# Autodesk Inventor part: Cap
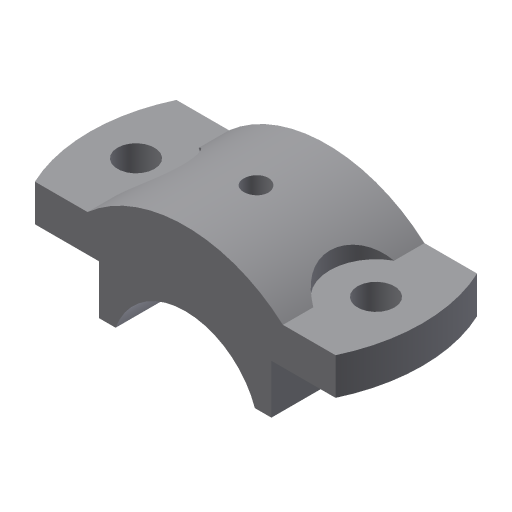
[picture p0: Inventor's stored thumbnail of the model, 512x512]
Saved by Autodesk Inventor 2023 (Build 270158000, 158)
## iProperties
Created: 2002-02
Part Number: Cap
Document SubType Name: Modeling
Designer: ***
Density: 1 g/cm^3
Material: Generic
Appearance: Default
Control State: 0
Master: False
Checked Out: False
Shininess: 77.0
Angle Display Precision: 2
Document Length Units: 11269
Document Angle Units: 11279
Document Time Units: 11290
Document Mass Units: 11283
Document Length Units Precision: 3
Document Angle Units Precision: 2
Density: 0.0
Volumn: 0.0
Area: 0.0
PropertySet Name: Model Information
Author: ***
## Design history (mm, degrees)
sketch "Sketch2"
  geometry: L1 (22.656, 22.99)-(28.029, 22.99); L2 (28.029, 22.99)-(28.029, 38.99); L3 (28.029, 38.99)-(54.029, 38.99); L4 (54.029, 38.99)-(54.029, 50.99); L5 (54.029, 50.99)-(31.778, 50.99); L6 (-22.599, 22.99)-(-27.971, 22.99); L7 (-27.971, 22.99)-(-27.971, 38.99); L8 (-27.971, 38.99)-(-53.971, 38.99); L9 (-53.971, 38.99)-(-53.971, 50.99); L10 (-53.971, 50.99)-(-31.72, 50.99); A1 r 24 centre (0.029, 14.99) between (22.656, 22.99) and (-22.599, 22.99); A2 r 48 centre (0.029, 14.99) between (31.778, 50.99) and (-31.72, 50.99)
  constraints: 20 end point, 5 equal length, 4 parallel, 4 perpendicular, 4 point on circle, 2 centre point, 1 coincident, 1 horizontal, 1 point on line
  dimensions: "d0" = 24 radius of A1; "d1" = 8 distance from line of L1 A1.centre; "d2" = 12 distance of L8.end L9.end; "d3" = 16 distance of L6.end L7.end; "d4" = 48 radius of A2; "d5" = 108 distance between parallel lines of L9 L4; "d6" = 56 distance between parallel lines of L7 L2
extrude "Extrusion1" new body sketch "Sketch2" stored distance "d7" = 46; taper "d8" = 0 deg
sketch "Sketch3"
  geometry: L1 (17.108, 0)-(40.349, 0); L2 (40.349, 0)-(40.349, -46); L3 (40.349, -46)-(17.108, -46); L4 (0, -46)-(22.251, -46) reference; L5 (22.251, 0)-(0, 0) reference; L6 (22.251, 0)-(22.251, -46) reference; A1 r 54 centre (-31.749, -23) between (17.108, -46) and (17.108, 0)
  constraints: 6 end point, 2 collinear, 2 point on circle, 1 centre point, 1 horizontal, 1 parallel, 1 perpendicular, 1 vertical alignment
  dimensions: "d9" = 54 radius of A1; "d10" = 54 distance from line of L6 A1.centre
extrude "Extrusion2" cut sketch "Sketch3" extent not by distance; stored distance "d11" = 46; taper "d12" = 0 deg
sketch "Sketch4"
  geometry: L1 (17.108, 46)-(0, 46) reference; A1 r 54 centre (-31.749, 23) between (17.108, 0) and (17.108, 46) reference; 1 further point
  dimensions: "d13" = 23 distance from line of L1 point (7.251, 23); "d14" = 39 distance of A1.centre point (7.251, 23)
hole "Hole1" sketch "Sketch4" diameter "d15" = 30; stored, may be unused: countersink angle "d19" = 82 deg, drill point angle "d21" = 118 deg; dims "d16" = 6, "d17" = 4, "d18" = 2, "d20" = 8
hole "Hole2" sketch "Sketch4" diameter "d22" = 12; stored, may be unused: countersink angle "d26" = 82 deg, drill point angle "d28" = 118 deg; dims "d23" = 6, "d24" = 4, "d25" = 2, "d27" = 8
workplane "Work Plane1"
mirror "Mirror1"
workplane "Work Plane2"
sketch "Sketch5"
  geometry: L1 (31.749, -23)-(-31.749, -23) reference; C1 r 6 at (39, 0) reference; 1 further point
  dimensions: "d30" = 23 distance from line of L1 point (0, 0); "d31" = 39 distance of C1.centre point (0, 0)
hole "Hole3" sketch "Sketch5" at (0, 0) diameter "d32" = 6; stored, may be unused: countersink angle "d36" = 82 deg, drill point angle "d38" = 118 deg; dims "d33" = 6, "d34" = 8, "d35" = 16, "d37" = 8
body "Solid1"
other parameters: "d29" = -54
